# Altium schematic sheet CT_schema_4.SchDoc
size 334 x 183 mm
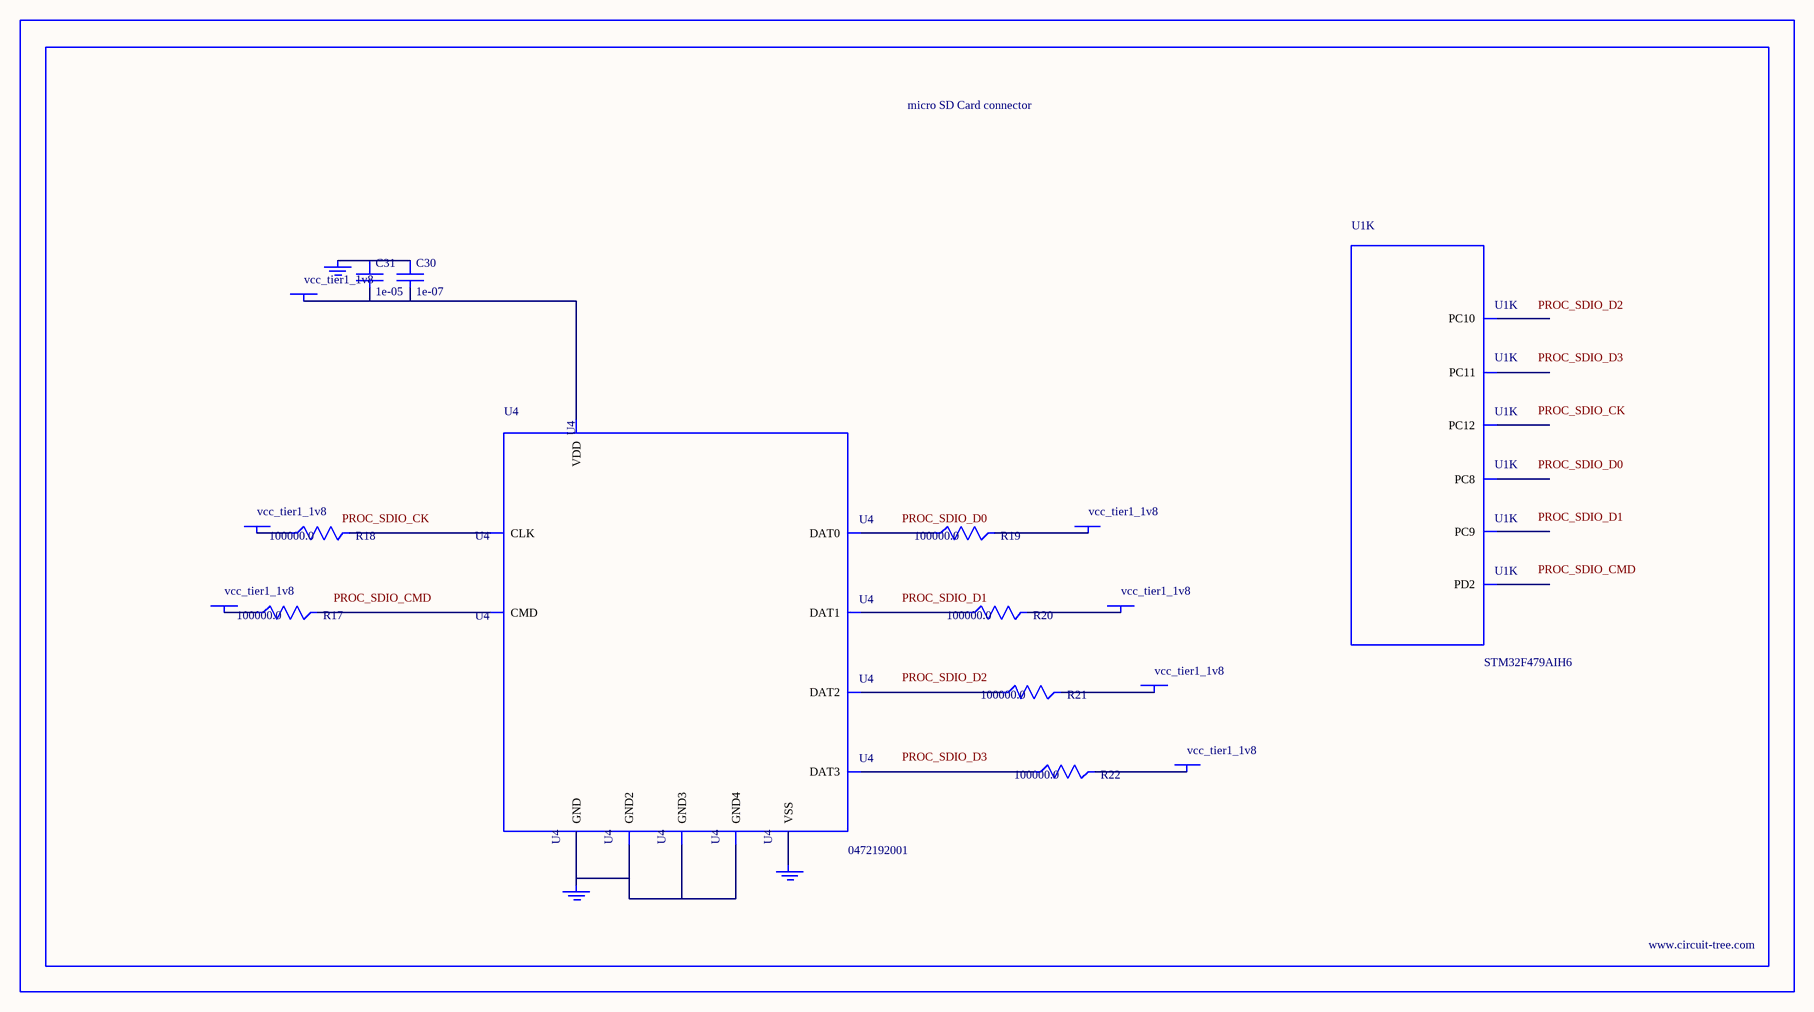
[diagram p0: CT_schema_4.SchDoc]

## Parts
BORDER3  (no value)
C30  1e-07  [C0402]
C31  1e-05  [C0805]
GND_INSTANCE_3_0  (no value)
GND_INSTANCE_3_1  (no value)
GND_INSTANCE_3_2  (no value)
POWER_INSTANCE_3_0  vcc_tier1_1v8
POWER_INSTANCE_3_1  vcc_tier1_1v8
POWER_INSTANCE_3_2  vcc_tier1_1v8
POWER_INSTANCE_3_3  vcc_tier1_1v8
POWER_INSTANCE_3_4  vcc_tier1_1v8
POWER_INSTANCE_3_5  vcc_tier1_1v8
POWER_INSTANCE_3_6  vcc_tier1_1v8
R17  100000.0  [R0603]
R18  100000.0  [R0603]
R19  100000.0  [R0603]
R20  100000.0  [R0603]
R21  100000.0  [R0603]
R22  100000.0  [R0603]
U1  STM32F479AIH6  [UFBGA169]  (part K of 14)
U4  0472192001  [MOLEX_47219-2001]

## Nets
NetC30_1: C30.1 C31.1 GND_INSTANCE_3_0.0(GND)
NetC30_2: C30.2 C31.2 POWER_INSTANCE_3_3.0(PWR) U4.4(VDD)
NetGND_INSTANCE_3_1_0: GND_INSTANCE_3_1.0(GND) U4.6(VSS)
NetGND_INSTANCE_3_2_0: GND_INSTANCE_3_2.0(GND) U4.G1(GND) U4.G2(GND2) U4.G3(GND3) U4.G4(GND4)
NetPOWER_INSTANCE_3_0_0: POWER_INSTANCE_3_0.0(PWR) R21.2
NetPOWER_INSTANCE_3_1_0: POWER_INSTANCE_3_1.0(PWR) R22.2
NetPOWER_INSTANCE_3_2_0: POWER_INSTANCE_3_2.0(PWR) R17.1
NetPOWER_INSTANCE_3_4_0: POWER_INSTANCE_3_4.0(PWR) R18.1
NetPOWER_INSTANCE_3_5_0: POWER_INSTANCE_3_5.0(PWR) R19.2
NetPOWER_INSTANCE_3_6_0: POWER_INSTANCE_3_6.0(PWR) R20.2
NetR17_2: R17.2 U4.3(CMD)
NetR18_2: R18.2 U4.5(CLK)
NetR19_1: R19.1 U4.7(DAT0)
NetR20_1: R20.1 U4.8(DAT1)
NetR21_1: R21.1 U4.1(DAT2)
NetR22_1: R22.1 U4.2(DAT3)

Not connected (* = marked no-connect by the designer): U1 A9(PC12) B8(PD2) B9(PC11) C10(PC10) E10(PC8) G10(PC9)

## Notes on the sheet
- Labels drawn without touching a wire or pin: PROC_SDIO_CK, PROC_SDIO_CMD, PROC_SDIO_D0, PROC_SDIO_D1, PROC_SDIO_D2, PROC_SDIO_D3

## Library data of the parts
BORDER3 = BORDER_PAGE3
C30 = C0402C104K3RACTU
C31 = C0805C106K8RACTU
GND_INSTANCE_3_0-GND_INSTANCE_3_2 = GND
POWER_INSTANCE_3_0-POWER_INSTANCE_3_6 = PWR
R17-R22 = RC0603JR-07100KL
